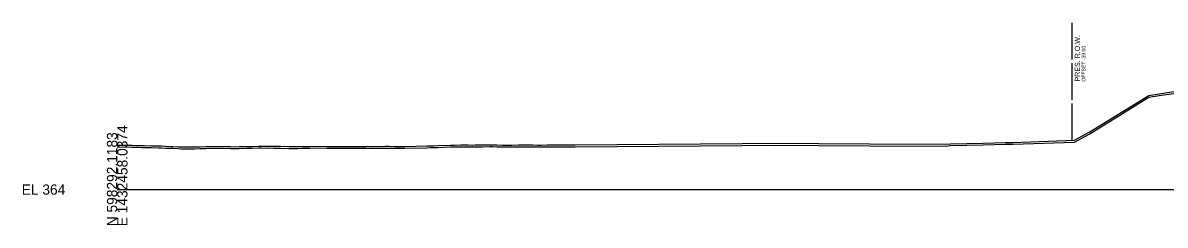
# Model space of a CAD drawing. Extents: x -26 to 2203, y -10 to 12201.
# Drawn here: x -25.7 to 285.3, y 3990.3 to 4045.4 of the extents above; entities that cross this region are included whole.
import ezdxf

# ---------------------------------------------------------------- set-up
doc = ezdxf.new("R2010")
doc.units = 0
for name, color, linetype in [('DESIGN - SHEET - Light Grid', 7, 'Continuous'), ('SURVEY - GROUND - Bottom of Topsoil Layer', 7, 'Continuous'), ('SURVEY - GROUND - Top of Ground', 7, 'Continuous'), ('SURVEY - PROPERTY - ROW Lines', 7, 'Continuous'), ('SURVEY - PROPERTY - ROW Lines Text', 7, 'Continuous')]:
    doc.layers.add(name, color=color, linetype=linetype)

msp = doc.modelspace()

# ---------------------------------------------------------------- linework, layer by layer
at = {"layer": 'DESIGN - SHEET - Light Grid'}
msp.add_line((0, 4000), (300, 4000), dxfattribs=at)
at = {"layer": 'SURVEY - GROUND - Bottom of Topsoil Layer'}
for p, q in [((264.65, 4015.1), (280.91, 4025.15)), ((280.91, 4025.15), (283.7, 4025.58)), ((283.7, 4025.58), (288.94, 4026.38)), ((243.85, 4012.36), (260.69, 4012.92)), ((260.69, 4012.92), (264.65, 4015.1)), ((0, 4011.59), (1.55, 4011.61)), ((1.55, 4011.61), (4.08, 4011.57)), ((4.08, 4011.57), (5.38, 4011.51)), ((5.38, 4011.51), (6.73, 4011.49)), ((6.73, 4011.49), (7.34, 4011.47)), ((7.34, 4011.47), (9.38, 4011.43)), ((9.38, 4011.43), (11.26, 4011.38)), ((11.26, 4011.38), (12.03, 4011.37)), ((12.03, 4011.37), (13.22, 4011.3)), ((13.22, 4011.3), (14.68, 4011.25)), ((14.68, 4011.25), (15.18, 4011.24)), ((15.18, 4011.24), (16.6, 4011.15)), ((16.6, 4011.15), (17.33, 4011.1)), ((17.33, 4011.1), (19.1, 4011.11)), ((19.1, 4011.11), (19.98, 4011.1)), ((19.98, 4011.1), (21.06, 4011.13)), ((21.06, 4011.13), (22.63, 4011.15)), ((22.63, 4011.15), (24.12, 4011.2)), ((24.12, 4011.2), (25.53, 4011.23)), ((25.53, 4011.23), (30.86, 4011.2)), ((30.86, 4011.2), (31.87, 4011.18)), ((31.87, 4011.18), (33.23, 4011.19)), ((33.23, 4011.19), (35.18, 4011.24)), ((35.18, 4011.24), (36.74, 4011.26)), ((36.74, 4011.26), (38.53, 4011.33)), ((38.53, 4011.33), (39.18, 4011.33)), ((39.18, 4011.33), (40.66, 4011.31)), ((40.66, 4011.31), (41.18, 4011.33)), ((41.18, 4011.33), (42.62, 4011.3)), ((42.62, 4011.3), (43.84, 4011.29)), ((43.84, 4011.29), (44.58, 4011.28)), ((44.58, 4011.28), (46.7, 4011.21)), ((46.7, 4011.21), (48.5, 4011.19)), ((48.5, 4011.19), (49.14, 4011.19)), ((49.14, 4011.19), (50.46, 4011.24)), ((50.46, 4011.24), (51.79, 4011.25)), ((51.79, 4011.25), (52.42, 4011.26)), ((52.42, 4011.26), (54.55, 4011.32)), ((54.55, 4011.32), (57.09, 4011.27)), ((57.09, 4011.27), (58.64, 4011.25)), ((58.64, 4011.25), (59.74, 4011.24)), ((59.74, 4011.24), (61.76, 4011.25)), ((61.76, 4011.25), (62.39, 4011.25)), ((62.39, 4011.25), (62.73, 4011.25)), ((62.73, 4011.25), (65.04, 4011.27)), ((65.04, 4011.27), (66.15, 4011.27)), ((66.15, 4011.27), (67.69, 4011.27)), ((67.69, 4011.27), (68.11, 4011.28)), ((68.11, 4011.28), (69.28, 4011.27)), ((69.28, 4011.27), (70.34, 4011.28)), ((70.34, 4011.28), (72.03, 4011.27)), ((72.03, 4011.27), (72.99, 4011.29)), ((72.99, 4011.29), (73.99, 4011.29)), ((73.99, 4011.29), (75.64, 4011.24)), ((75.64, 4011.24), (75.95, 4011.25)), ((75.95, 4011.25), (76.81, 4011.25)), ((76.81, 4011.25), (77.91, 4011.26)), ((77.91, 4011.26), (78.29, 4011.26)), ((78.29, 4011.26), (84.34, 4011.39)), ((84.34, 4011.39), (85.27, 4011.41)), ((85.27, 4011.41), (85.59, 4011.41)), ((85.59, 4011.41), (86.25, 4011.43)), ((86.25, 4011.43), (87.28, 4011.47)), ((87.28, 4011.47), (90.79, 4011.6)), ((90.79, 4011.6), (91.55, 4011.62)), ((91.55, 4011.62), (91.86, 4011.63)), ((91.86, 4011.63), (93.59, 4011.64)), ((93.59, 4011.64), (94.2, 4011.66)), ((94.2, 4011.66), (95.55, 4011.65)), ((95.55, 4011.65), (96.85, 4011.63)), ((96.85, 4011.63), (97.51, 4011.64)), ((97.51, 4011.64), (99.5, 4011.68)), ((99.5, 4011.68), (101.43, 4011.69)), ((101.43, 4011.69), (102.15, 4011.69)), ((102.15, 4011.69), (103.39, 4011.64)), ((103.39, 4011.64), (104.8, 4011.63)), ((104.8, 4011.63), (105.35, 4011.62)), ((105.35, 4011.62), (106.92, 4011.63)), ((106.92, 4011.63), (107.45, 4011.63)), ((107.45, 4011.63), (109.27, 4011.64)), ((109.27, 4011.64), (110.1, 4011.66)), ((110.1, 4011.66), (111.23, 4011.64)), ((111.23, 4011.64), (112.75, 4011.65)), ((112.75, 4011.65), (113.19, 4011.64)), ((113.19, 4011.64), (114.44, 4011.63)), ((114.44, 4011.63), (115.4, 4011.62)), ((115.4, 4011.62), (117.11, 4011.65)), ((117.11, 4011.65), (118.53, 4011.65)), ((118.53, 4011.65), (119.18, 4011.65)), ((119.18, 4011.65), (122.45, 4011.66)), ((122.45, 4011.66), (124.67, 4011.68)), ((124.67, 4011.68), (170.17, 4012.02)), ((170.17, 4012.02), (177.25, 4012.12)), ((177.25, 4012.12), (204.8, 4011.92)), ((204.8, 4011.92), (225.48, 4011.85)), ((225.48, 4011.85), (226.94, 4011.96)), ((226.94, 4011.96), (235.77, 4012.14)), ((235.77, 4012.14), (241.92, 4012.33)), ((241.92, 4012.33), (243.85, 4012.36))]:
    msp.add_line(p, q, dxfattribs=at)
at = {"layer": 'SURVEY - GROUND - Top of Ground'}
for p, q in [((264.65, 4015.6), (280.91, 4025.65)), ((280.91, 4025.65), (283.7, 4026.08)), ((283.7, 4026.08), (288.94, 4026.88)), ((260.69, 4013.42), (264.65, 4015.6)), ((124.67, 4012.18), (170.17, 4012.52)), ((170.17, 4012.52), (177.25, 4012.62)), ((177.25, 4012.62), (204.8, 4012.42)), ((225.48, 4012.35), (226.94, 4012.46)), ((226.94, 4012.46), (235.77, 4012.64)), ((235.77, 4012.64), (241.92, 4012.83)), ((241.92, 4012.83), (243.85, 4012.86)), ((243.85, 4012.86), (260.69, 4013.42)), ((0, 4012.09), (1.55, 4012.11)), ((1.55, 4012.11), (4.08, 4012.07)), ((4.08, 4012.07), (5.38, 4012.01)), ((5.38, 4012.01), (6.73, 4011.99)), ((6.73, 4011.99), (7.34, 4011.97)), ((7.34, 4011.97), (9.38, 4011.93)), ((9.38, 4011.93), (11.26, 4011.88)), ((11.26, 4011.88), (12.03, 4011.87)), ((12.03, 4011.87), (13.22, 4011.8)), ((13.22, 4011.8), (14.68, 4011.75)), ((14.68, 4011.75), (15.18, 4011.74)), ((15.18, 4011.74), (16.6, 4011.65)), ((16.6, 4011.65), (17.33, 4011.6)), ((17.33, 4011.6), (19.1, 4011.61)), ((19.1, 4011.61), (19.98, 4011.6)), ((19.98, 4011.6), (21.06, 4011.63)), ((21.06, 4011.63), (22.63, 4011.65)), ((22.63, 4011.65), (24.12, 4011.7)), ((24.12, 4011.7), (25.53, 4011.73)), ((25.53, 4011.73), (30.86, 4011.7)), ((30.86, 4011.7), (31.87, 4011.68)), ((31.87, 4011.68), (33.23, 4011.69)), ((33.23, 4011.69), (35.18, 4011.74)), ((35.18, 4011.74), (36.74, 4011.76)), ((36.74, 4011.76), (38.53, 4011.83)), ((38.53, 4011.83), (39.18, 4011.83)), ((39.18, 4011.83), (40.66, 4011.81)), ((40.66, 4011.81), (41.18, 4011.83)), ((41.18, 4011.83), (42.62, 4011.8)), ((42.62, 4011.8), (43.84, 4011.79)), ((43.84, 4011.79), (44.58, 4011.78)), ((44.58, 4011.78), (46.7, 4011.71)), ((46.7, 4011.71), (48.5, 4011.69)), ((48.5, 4011.69), (49.14, 4011.69)), ((49.14, 4011.69), (50.46, 4011.74)), ((50.46, 4011.74), (51.79, 4011.75)), ((51.79, 4011.75), (52.42, 4011.76)), ((52.42, 4011.76), (54.55, 4011.82)), ((54.55, 4011.82), (57.09, 4011.77)), ((57.09, 4011.77), (58.64, 4011.75)), ((58.64, 4011.75), (59.74, 4011.74)), ((59.74, 4011.74), (61.76, 4011.75)), ((61.76, 4011.75), (62.39, 4011.75)), ((62.39, 4011.75), (62.73, 4011.75)), ((62.73, 4011.75), (65.04, 4011.77)), ((65.04, 4011.77), (66.15, 4011.77)), ((66.15, 4011.77), (67.69, 4011.77)), ((67.69, 4011.77), (68.11, 4011.78)), ((68.11, 4011.78), (69.28, 4011.77)), ((69.28, 4011.77), (70.34, 4011.78)), ((70.34, 4011.78), (72.03, 4011.77)), ((72.03, 4011.77), (72.99, 4011.79)), ((72.99, 4011.79), (73.99, 4011.79)), ((73.99, 4011.79), (75.64, 4011.74)), ((75.64, 4011.74), (75.95, 4011.75)), ((75.95, 4011.75), (76.81, 4011.75)), ((76.81, 4011.75), (77.91, 4011.76)), ((77.91, 4011.76), (78.29, 4011.76)), ((78.29, 4011.76), (84.34, 4011.89)), ((84.34, 4011.89), (85.27, 4011.91)), ((85.27, 4011.91), (85.59, 4011.91)), ((85.59, 4011.91), (86.25, 4011.93)), ((86.25, 4011.93), (87.28, 4011.97)), ((87.28, 4011.97), (90.79, 4012.1)), ((90.79, 4012.1), (91.55, 4012.12)), ((91.55, 4012.12), (91.86, 4012.13)), ((91.86, 4012.13), (93.59, 4012.14)), ((93.59, 4012.14), (94.2, 4012.16)), ((94.2, 4012.16), (95.55, 4012.15)), ((95.55, 4012.15), (96.85, 4012.13)), ((96.85, 4012.13), (97.51, 4012.14)), ((97.51, 4012.14), (99.5, 4012.18)), ((99.5, 4012.18), (101.43, 4012.19)), ((101.43, 4012.19), (102.15, 4012.19)), ((102.15, 4012.19), (103.39, 4012.14)), ((103.39, 4012.14), (104.8, 4012.13)), ((104.8, 4012.13), (105.35, 4012.12)), ((105.35, 4012.12), (106.92, 4012.13)), ((106.92, 4012.13), (107.45, 4012.13)), ((107.45, 4012.13), (109.27, 4012.14)), ((109.27, 4012.14), (110.1, 4012.16)), ((110.1, 4012.16), (111.23, 4012.14)), ((111.23, 4012.14), (112.75, 4012.15)), ((112.75, 4012.15), (113.19, 4012.14)), ((113.19, 4012.14), (114.44, 4012.13)), ((114.44, 4012.13), (115.4, 4012.12)), ((115.4, 4012.12), (117.11, 4012.15)), ((117.11, 4012.15), (118.53, 4012.15)), ((118.53, 4012.15), (119.18, 4012.15)), ((119.18, 4012.15), (122.45, 4012.16)), ((122.45, 4012.16), (124.67, 4012.18)), ((204.8, 4012.42), (225.48, 4012.35))]:
    msp.add_line(p, q, dxfattribs=at)
at = {"layer": 'SURVEY - PROPERTY - ROW Lines'}
for p, q in [((260, 4035.4), (260, 4045.4)), ((260, 4024.4), (260, 4034.4)), ((260, 4013.4), (260, 4023.4))]:
    msp.add_line(p, q, dxfattribs=at)

# ---------------------------------------------------------------- texts
at = {"layer": 'DESIGN - SHEET - Light Grid'}
for s, p in [('E 1432458.0374', (2.8, 3990)), ('N 598292.1183', (0, 3990))]:
    msp.add_text(s, height=2.8, rotation=90, dxfattribs=at).set_placement(p)
msp.add_text('EL 364', height=2.8, dxfattribs=at).set_placement((-26, 3998.6))
at = {"layer": 'SURVEY - PROPERTY - ROW Lines Text'}
for s, height, p in [('PRES. R.O.W.', 1.4, (262.15, 4029.4)), ('OFFSET -39.00', 1, (263.65, 4029.4))]:
    msp.add_text(s, height=height, rotation=90, dxfattribs=at).set_placement(p)

doc.saveas('drawing.dxf')
